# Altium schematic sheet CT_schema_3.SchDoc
size 461 x 327 mm
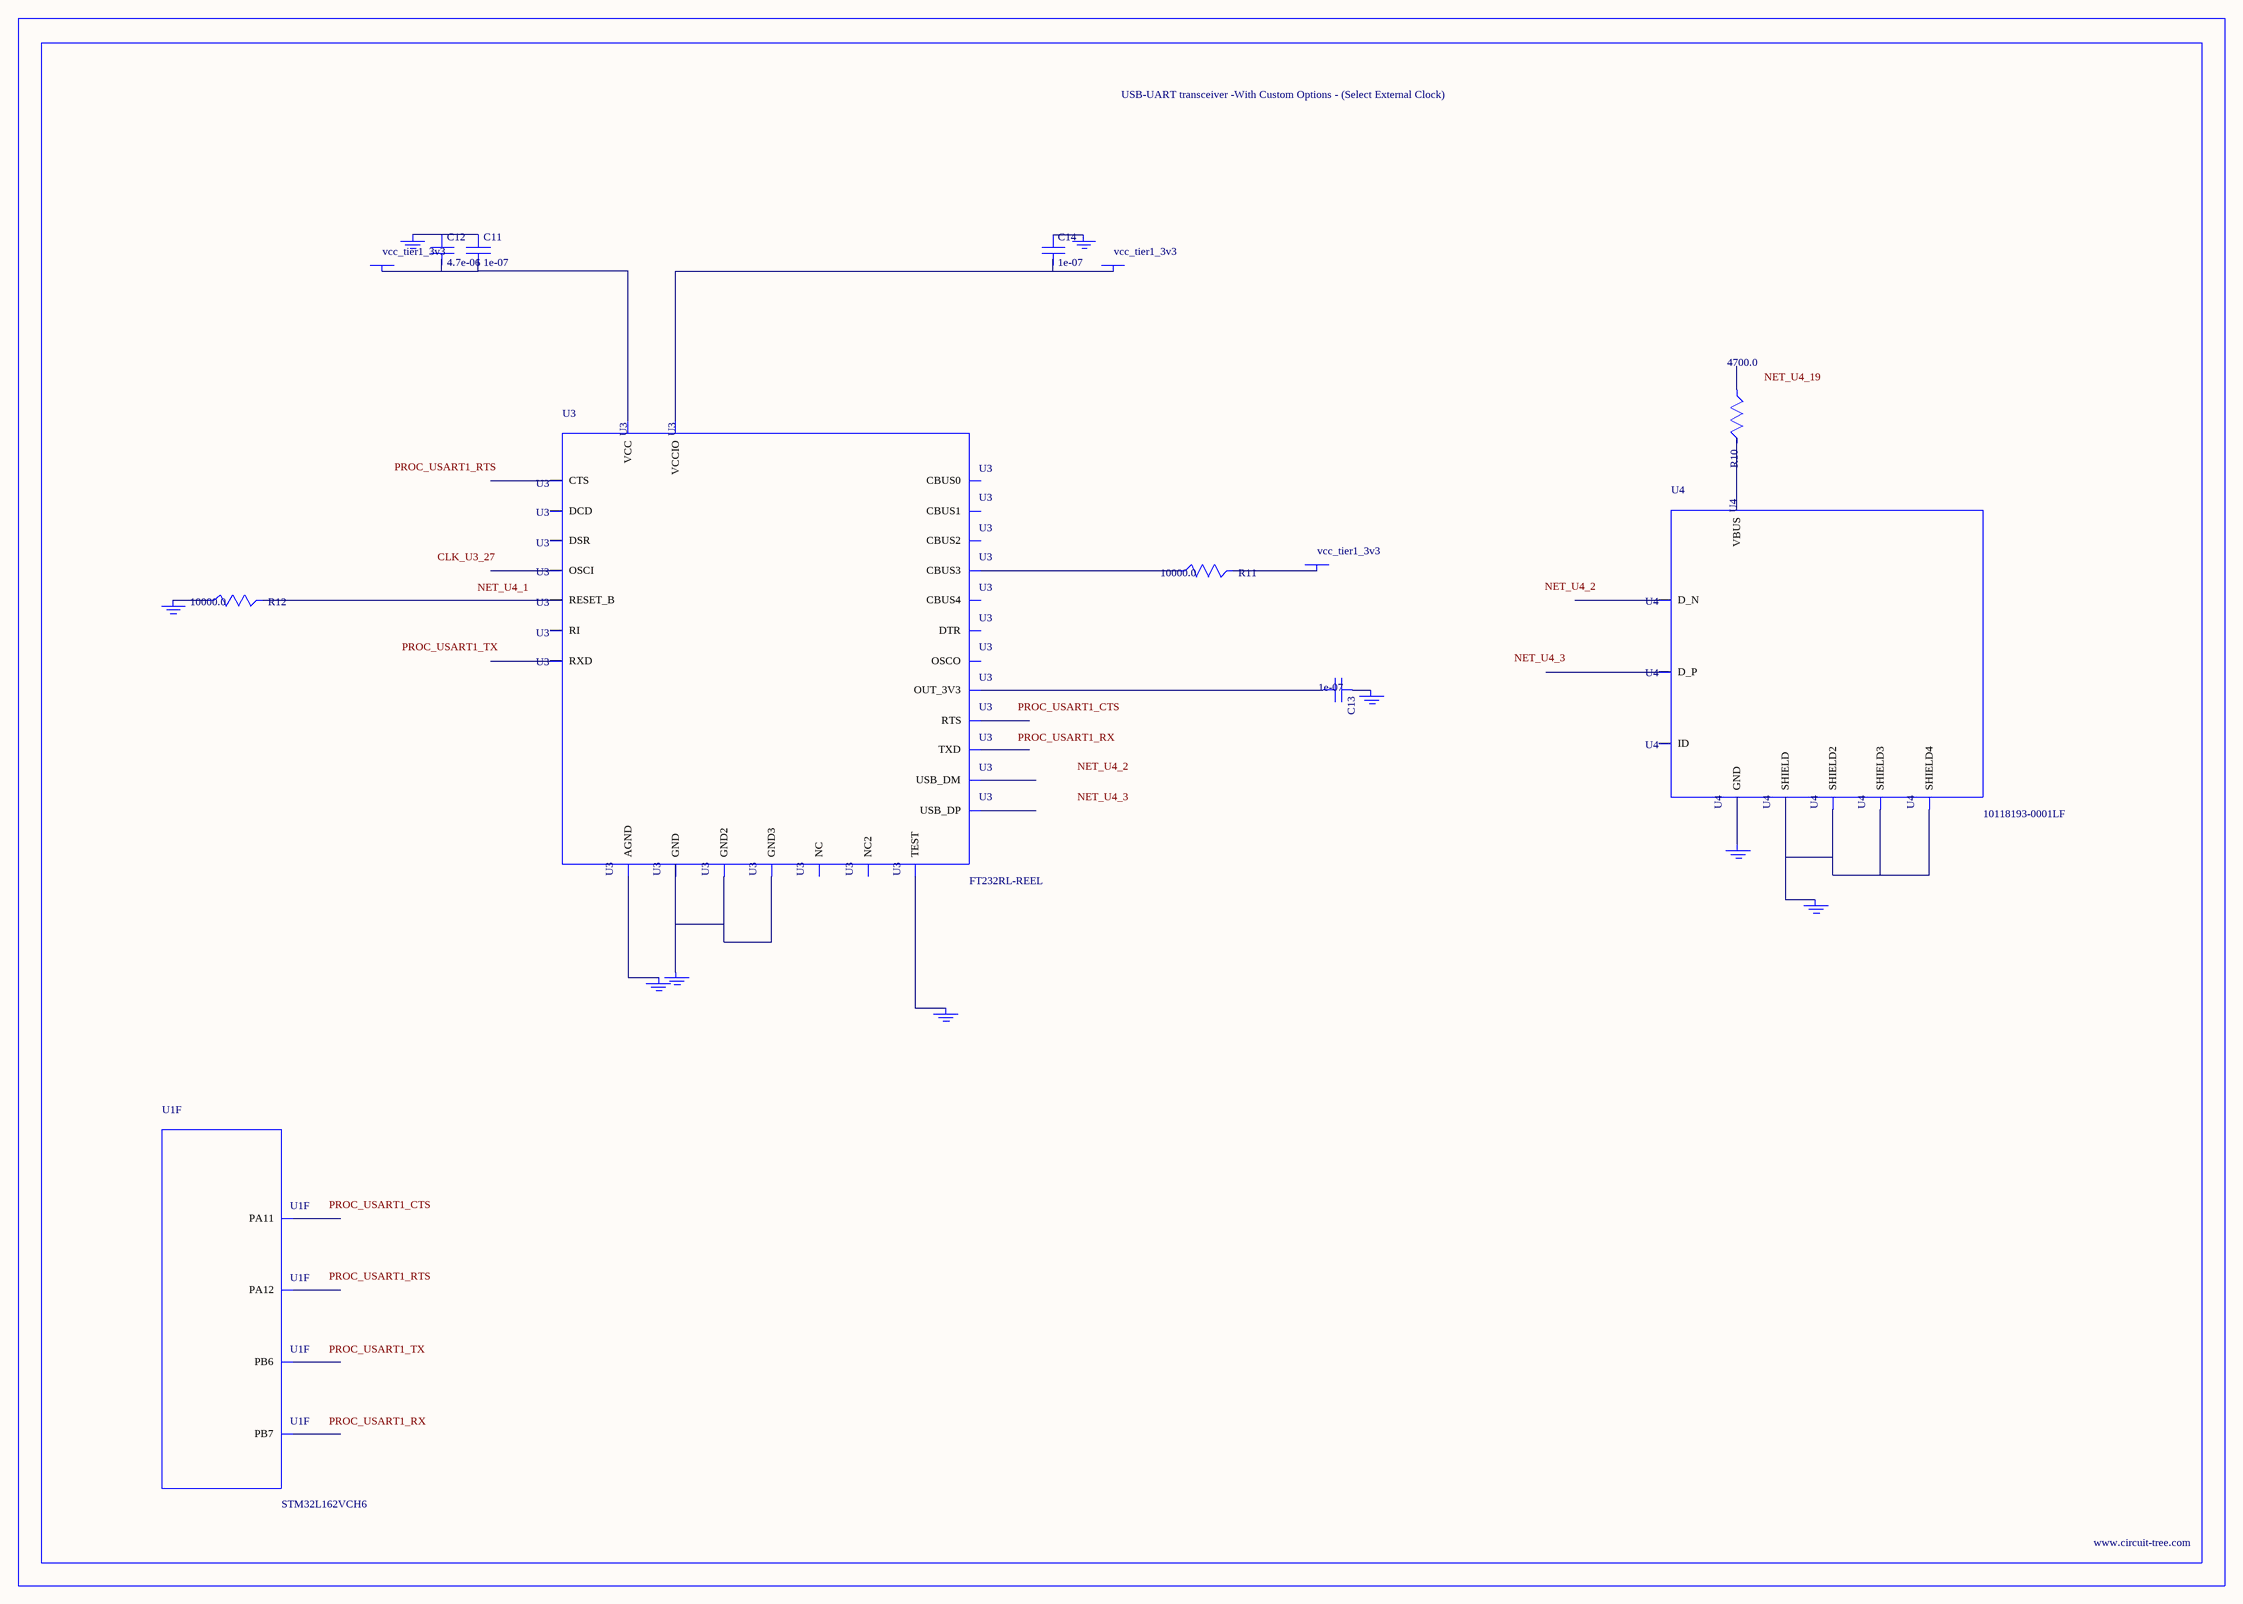
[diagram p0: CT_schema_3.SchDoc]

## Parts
BORDER2  (no value)
C11  1e-07  [C0402]
C12  4.7e-06  [C0805]
C13  1e-07  [C0402]
C14  1e-07  [C0402]
GND_INSTANCE_2_0  (no value)
GND_INSTANCE_2_1  (no value)
GND_INSTANCE_2_2  (no value)
GND_INSTANCE_2_3  (no value)
GND_INSTANCE_2_4  (no value)
GND_INSTANCE_2_5  (no value)
GND_INSTANCE_2_6  (no value)
GND_INSTANCE_2_7  (no value)
GND_INSTANCE_2_8  (no value)
POWER_INSTANCE_2_0  vcc_tier1_3v3
POWER_INSTANCE_2_1  vcc_tier1_3v3
POWER_INSTANCE_2_2  vcc_tier1_3v3
R10  4700.0  [R0603]
R11  10000.0  [R0603]
R12  10000.0  [R0603]
U1  STM32L162VCH6  [UFBGA100]  (part F of 9)
U3  FT232RL-REEL  [SSOP-28]
U4  10118193-0001LF  [FCI_10118193-0001LF]

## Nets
NetC11_1: C11.1 C12.1 GND_INSTANCE_2_3.0(GND)
NetC11_2: C11.2 C12.2 POWER_INSTANCE_2_2.0(PWR) U3.20(VCC)
NetC13_1: C13.1 GND_INSTANCE_2_1.0(GND)
NetC13_2: C13.2 U3.17(OUT_3V3)
NetC14_1: C14.1 GND_INSTANCE_2_0.0(GND)
NetC14_2: C14.2 POWER_INSTANCE_2_0.0(PWR) U3.4(VCCIO)
NetGND_INSTANCE_2_2_0: GND_INSTANCE_2_2.0(GND) R12.1
NetGND_INSTANCE_2_4_0: GND_INSTANCE_2_4.0(GND) U3.25(AGND)
NetGND_INSTANCE_2_5_0: GND_INSTANCE_2_5.0(GND) U3.26(TEST)
NetGND_INSTANCE_2_6_0: GND_INSTANCE_2_6.0(GND) U3.7(GND) U3.18(GND2) U3.21(GND3)
NetGND_INSTANCE_2_7_0: GND_INSTANCE_2_7.0(GND) U4.6(SHIELD) U4.7(SHIELD2) U4.8(SHIELD3) U4.9(SHIELD4)
NetGND_INSTANCE_2_8_0: GND_INSTANCE_2_8.0(GND) U4.5(GND)
NetPOWER_INSTANCE_2_1_0: POWER_INSTANCE_2_1.0(PWR) R11.2
NetR10_2: R10.2 U4.1(VBUS)
NetR11_1: R11.1 U3.14(CBUS3)
NetR12_2: R12.2 U3.19(RESET_B)

Not connected (* = marked no-connect by the designer): R10 1; U1 A12(PA12) B4(PB7) B5(PB6) B12(PA11); U3 1(TXD) 2(DTR) 3(RTS) 5(RXD) 6(RI) 8(NC) 9(DSR) 10(DCD) 11(CTS) 12(CBUS4) 13(CBUS2) 15(USB_DP) 16(USB_DM) 22(CBUS1) 23(CBUS0) 24(NC2) 27(OSCI) 28(OSCO); U4 2(D_N) 3(D_P) 4(ID)

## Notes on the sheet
- Labels drawn without touching a wire or pin: CLK_U3_27, NET_U4_1, NET_U4_2, NET_U4_3, NET_U4_19, PROC_USART1_CTS, PROC_USART1_RTS, PROC_USART1_RX, PROC_USART1_TX

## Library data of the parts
BORDER2 = BORDER_PAGE2
C11 C13 C14 = C0402C104K3RACTU
C12 = C0805C475K4RACTU
GND_INSTANCE_2_0-GND_INSTANCE_2_8 = GND
POWER_INSTANCE_2_0-POWER_INSTANCE_2_2 = PWR
R10 = RC0603JR-074K7L
R11 R12 = RC0603JR-0710KL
